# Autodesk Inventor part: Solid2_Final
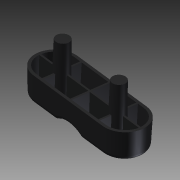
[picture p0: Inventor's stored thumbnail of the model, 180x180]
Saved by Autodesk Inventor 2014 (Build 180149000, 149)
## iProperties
Created: 2009-02
Part Number: Solid2_Final
Document SubType Name: Modeling
Designer: Autodesk
Density: 1 g/cm^3
Material: Generic
Appearance: Default
Author: Autodesk
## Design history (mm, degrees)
derived "Side Panel Handle.ipt"
body "Solid1"
feature "Solid2::Side Panel Handle.ipt" dims "d0" = 10
tag "TaggingFeature1"
